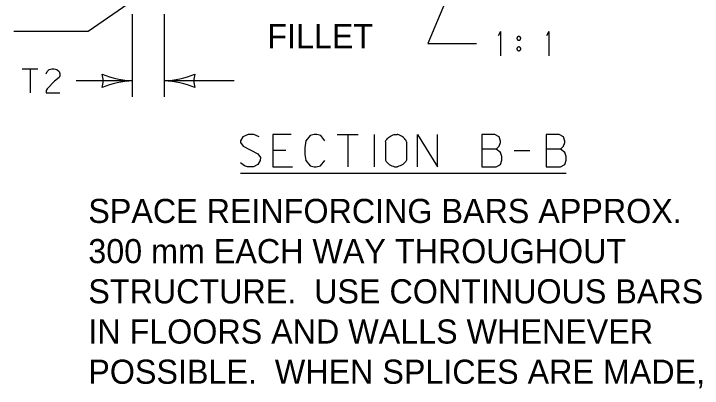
# Model space of a CAD drawing. Extents: x 49991.4 to 50043, y 49987.6 to 50011.4.
# Drawn here: x 50038.288 to 50040, y 49996.223 to 49997.154 of the extents above; entities that cross this region are included whole.
import ezdxf

# ---------------------------------------------------------------- set-up
doc = ezdxf.new("R2010")
doc.units = 0
doc.layers.add('Level 2', color=7, linetype='Continuous')
doc.layers.add('Level 3', color=7, linetype='Continuous')

msp = doc.modelspace()

# ---------------------------------------------------------------- linework, layer by layer
at = {"layer": 'Level 2'}
for p, q in [((50039.498, 49997.11), (50039.4921, 49997.0996)), ((50039.498, 49997.11), (50039.498, 49997.05)), ((50039.618, 49997.11), (50039.6121, 49997.0996)), ((50039.618, 49997.11), (50039.618, 49997.05)), ((50038.3084, 49997.0174), (50038.3477, 49997.0174)), ((50038.3283, 49997.0174), (50038.3283, 49996.9574)), ((50039.0915, 49996.8538), (50039.1438, 49996.8538)), ((50039.118, 49996.8538), (50039.118, 49996.7738)), ((50039.1844, 49996.7738), (50039.1844, 49996.8538)), ((50039.2348, 49996.8538), (50039.2411, 49996.8538)), ((50039.2115, 49996.8361), (50039.2115, 49996.7901)), ((50039.2644, 49996.8361), (50039.2644, 49996.7901)), ((50038.9643, 49996.8141), (50038.9315, 49996.8141)), ((50039.5315, 49996.8141), (50039.5706, 49996.8141)), ((50039.2348, 49996.7738), (50039.2411, 49996.7738)), ((50038.8515, 49996.7578), (50039.6613, 49996.7578))]:
    msp.add_line(p, q, dxfattribs=at)
for points in [[(50039.5482, 49997.0931), (50039.5482, 49997.0936), (50039.5481, 49997.0941), (50039.548, 49997.0946), (50039.5478, 49997.0951), (50039.5476, 49997.0955), (50039.5473, 49997.0959), (50039.547, 49997.0963), (50039.5466, 49997.0966), (50039.5463, 49997.0969), (50039.5458, 49997.0972), (50039.5454, 49997.0974), (50039.5449, 49997.0976), (50039.5445, 49997.0977), (50039.544, 49997.0978), (50039.5435, 49997.0979), (50039.543, 49997.0978), (50039.5425, 49997.0977), (50039.542, 49997.0976), (50039.5416, 49997.0974), (50039.5411, 49997.0972), (50039.5407, 49997.0969), (50039.5403, 49997.0966), (50039.54, 49997.0963), (50039.5397, 49997.0959), (50039.5394, 49997.0955), (50039.5392, 49997.0951), (50039.539, 49997.0946), (50039.5389, 49997.0941), (50039.5388, 49997.0936), (50039.5388, 49997.0931), (50039.5388, 49997.0926), (50039.5389, 49997.0921), (50039.539, 49997.0917), (50039.5392, 49997.0912), (50039.5394, 49997.0908), (50039.5397, 49997.0903), (50039.54, 49997.09), (50039.5403, 49997.0896), (50039.5407, 49997.0893), (50039.5411, 49997.089), (50039.5416, 49997.0888), (50039.542, 49997.0886), (50039.5425, 49997.0885), (50039.543, 49997.0884), (50039.5435, 49997.0884), (50039.544, 49997.0884), (50039.5445, 49997.0885), (50039.5449, 49997.0886), (50039.5454, 49997.0888), (50039.5458, 49997.089), (50039.5463, 49997.0893), (50039.5466, 49997.0896), (50039.547, 49997.09), (50039.5473, 49997.0903), (50039.5476, 49997.0908), (50039.5478, 49997.0912), (50039.548, 49997.0917), (50039.5481, 49997.0921), (50039.5482, 49997.0926), (50039.5482, 49997.0931)], [(50039.5482, 49997.0671), (50039.5482, 49997.0676), (50039.5481, 49997.0681), (50039.548, 49997.0686), (50039.5478, 49997.0691), (50039.5476, 49997.0695), (50039.5473, 49997.0699), (50039.547, 49997.0703), (50039.5466, 49997.0707), (50039.5463, 49997.071), (50039.5458, 49997.0712), (50039.5454, 49997.0715), (50039.5449, 49997.0716), (50039.5445, 49997.0718), (50039.544, 49997.0718), (50039.5435, 49997.0719), (50039.543, 49997.0718), (50039.5425, 49997.0718), (50039.542, 49997.0716), (50039.5416, 49997.0715), (50039.5411, 49997.0712), (50039.5407, 49997.071), (50039.5403, 49997.0707), (50039.54, 49997.0703), (50039.5397, 49997.0699), (50039.5394, 49997.0695), (50039.5392, 49997.0691), (50039.539, 49997.0686), (50039.5389, 49997.0681), (50039.5388, 49997.0676), (50039.5388, 49997.0671), (50039.5388, 49997.0666), (50039.5389, 49997.0662), (50039.539, 49997.0657), (50039.5392, 49997.0652), (50039.5394, 49997.0648), (50039.5397, 49997.0644), (50039.54, 49997.064), (50039.5403, 49997.0636), (50039.5407, 49997.0633), (50039.5411, 49997.0631), (50039.5416, 49997.0628), (50039.542, 49997.0626), (50039.5425, 49997.0625), (50039.543, 49997.0624), (50039.5435, 49997.0624), (50039.544, 49997.0624), (50039.5445, 49997.0625), (50039.5449, 49997.0626), (50039.5454, 49997.0628), (50039.5458, 49997.0631), (50039.5463, 49997.0633), (50039.5466, 49997.0636), (50039.547, 49997.064), (50039.5473, 49997.0644), (50039.5476, 49997.0648), (50039.5478, 49997.0652), (50039.548, 49997.0657), (50039.5481, 49997.0662), (50039.5482, 49997.0666), (50039.5482, 49997.0671)], [(50038.3684, 49997.0051), (50038.3703, 49997.0108), (50038.3755, 49997.0155), (50038.3826, 49997.0174), (50038.3878, 49997.0174), (50038.3949, 49997.0155), (50038.4001, 49997.0103), (50038.4025, 49997.0051), (50038.4025, 49996.9999), (50038.4006, 49996.9957), (50038.3888, 49996.9867), (50038.3703, 49996.9678), (50038.3684, 49996.9631), (50038.3684, 49996.9574), (50038.4025, 49996.9574)], [(50038.8975, 49996.8481), (50038.8849, 49996.8538), (50038.8704, 49996.8538), (50038.8572, 49996.8481), (50038.8515, 49996.838), (50038.8515, 49996.8342), (50038.8578, 49996.8248), (50038.8944, 49996.8059), (50038.9007, 49996.7971), (50038.9, 49996.7895), (50038.8944, 49996.7794), (50038.8837, 49996.7738), (50038.8685, 49996.7738), (50038.8616, 49996.7763), (50038.8515, 49996.7832)], [(50038.9775, 49996.8538), (50038.9315, 49996.8538), (50038.9315, 49996.7738), (50038.9807, 49996.7738)], [(50039.0613, 49996.838), (50039.0512, 49996.8513), (50039.0411, 49996.8538), (50039.0342, 49996.8538), (50039.0248, 49996.8513), (50039.0141, 49996.838), (50039.0115, 49996.8204), (50039.0115, 49996.8109), (50039.0115, 49996.8046), (50039.0122, 49996.799), (50039.0141, 49996.7889), (50039.0248, 49996.7763), (50039.0342, 49996.7738), (50039.0399, 49996.7738), (50039.0506, 49996.7763), (50039.0613, 49996.7889)], [(50039.2115, 49996.8361), (50039.2131, 49996.839), (50039.2149, 49996.8417), (50039.217, 49996.8442), (50039.2193, 49996.8465), (50039.2219, 49996.8485), (50039.2246, 49996.8502), (50039.2276, 49996.8517), (50039.2306, 49996.8528), (50039.2338, 49996.8536), (50039.2348, 49996.8538)], [(50039.2644, 49996.8361), (50039.2629, 49996.839), (50039.2611, 49996.8417), (50039.259, 49996.8442), (50039.2567, 49996.8465), (50039.2541, 49996.8485), (50039.2514, 49996.8502), (50039.2484, 49996.8517), (50039.2454, 49996.8528), (50039.2422, 49996.8536), (50039.2411, 49996.8538)], [(50039.2915, 49996.7738), (50039.2915, 49996.8538), (50039.3413, 49996.7738), (50039.3413, 49996.8538)], [(50039.4874, 49996.8172), (50039.4944, 49996.8248), (50039.4975, 49996.8342), (50039.4975, 49996.8374), (50039.4944, 49996.8481), (50039.4837, 49996.8538), (50039.4515, 49996.8538), (50039.4515, 49996.7738), (50039.4874, 49996.7738), (50039.4975, 49996.7794), (50039.5013, 49996.7901), (50039.5013, 49996.7996), (50039.4975, 49996.809), (50039.4874, 49996.8172), (50039.4515, 49996.8172)], [(50039.6474, 49996.8172), (50039.6544, 49996.8248), (50039.6575, 49996.8342), (50039.6575, 49996.8374), (50039.6544, 49996.8481), (50039.6437, 49996.8538), (50039.6115, 49996.8538), (50039.6115, 49996.7738), (50039.6474, 49996.7738), (50039.6575, 49996.7794), (50039.6613, 49996.7901), (50039.6613, 49996.7996), (50039.6575, 49996.809), (50039.6474, 49996.8172), (50039.6115, 49996.8172)], [(50039.2115, 49996.7901), (50039.2135, 49996.7871), (50039.2158, 49996.7844), (50039.2184, 49996.7818), (50039.2212, 49996.7796), (50039.2242, 49996.7777), (50039.2274, 49996.7761), (50039.2308, 49996.7748), (50039.2343, 49996.7739), (50039.2348, 49996.7738)], [(50039.2644, 49996.7901), (50039.2625, 49996.7871), (50039.2602, 49996.7844), (50039.2576, 49996.7818), (50039.2548, 49996.7796), (50039.2518, 49996.7777), (50039.2486, 49996.7761), (50039.2452, 49996.7748), (50039.2417, 49996.7739), (50039.2411, 49996.7738)]]:
    msp.add_lwpolyline(points, dxfattribs=at)
at = {"layer": 'Level 3'}
for p, q in [((50039.4192, 49997.3249), (50039.3175, 49997.08)), ((50038.6197, 49997.2124), (50038.4729, 49997.1102)), ((50038.5831, 49996.9474), (50038.5831, 49997.1535)), ((50038.6618, 49997.1535), (50038.6618, 49996.9474)), ((50038.4729, 49997.1102), (50038.2875, 49997.1102)), ((50039.3175, 49997.08), (50039.4386, 49997.08)), ((50038.5831, 49996.9874), (50038.4424, 49996.9874)), ((50038.8353, 49996.9874), (50038.6618, 49996.9874))]:
    msp.add_line(p, q, dxfattribs=at)
for centre, radius, start, end in [((50038.5923, 49997.2096), 0.2223, 247.456, 267.6395), ((50038.4549, 49996.9874), 0.0548, 342.1388, 17.8612), ((50038.6504, 49997.2201), 0.233, 272.8273, 292.0772), ((50038.7901, 49996.9874), 0.0548, 162.1388, 197.8612), ((50038.5946, 49996.7547), 0.233, 92.8273, 112.0772), ((50038.6527, 49996.7653), 0.2223, 67.456, 87.6395)]:
    msp.add_arc(centre, radius, start, end, dxfattribs=at)

# ---------------------------------------------------------------- texts
at = {"layer": 'Level 2'}
for s, p in [('FILLET', (50038.918, 49997.0685)), ('SPACE REINFORCING BARS APPROX.', (50038.4729, 49996.6338)), ('300 mm EACH WAY THROUGHOUT', (50038.4729, 49996.5338)), ('STRUCTURE.  USE CONTINUOUS BARS', (50038.4729, 49996.4338)), ('IN FLOORS AND WALLS WHENEVER', (50038.4729, 49996.3338)), ('POSSIBLE.  WHEN SPLICES ARE MADE,', (50038.4729, 49996.2338))]:
    msp.add_text(s, height=0.06, dxfattribs=at).set_placement(p)

doc.saveas('drawing.dxf')
